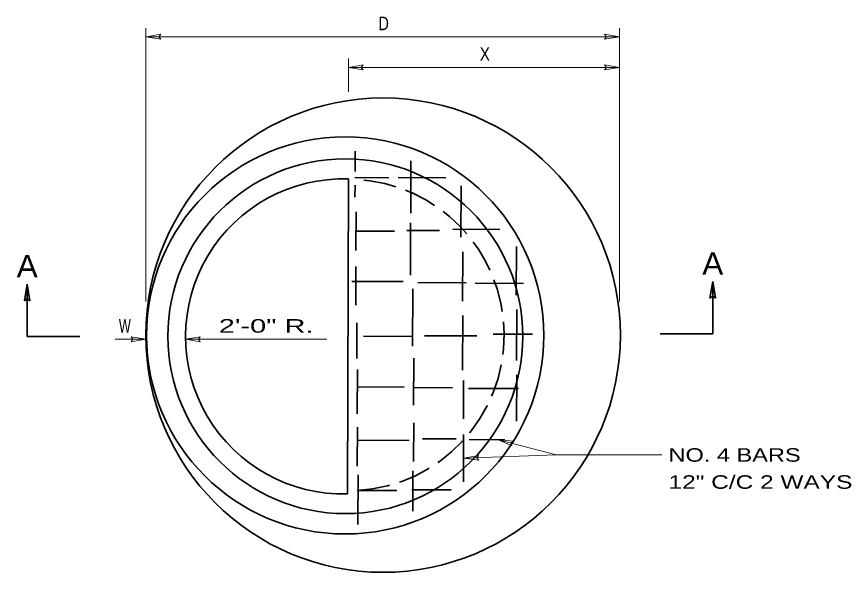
# Model space of a CAD drawing. Extents: x 5.1 to 20.2, y -16.7 to 4.3.
# Drawn here: x 8.84 to 16.79, y -1.01 to 4.29 of the extents above; entities that cross this region are included whole.
import ezdxf
from ezdxf.enums import TextEntityAlignment as Align

# ---------------------------------------------------------------- set-up
doc = ezdxf.new("R2010")
doc.units = 0
doc.header["$LTSCALE"] = 0.052
doc.linetypes.add('LONG_DASHED', pattern=[7.5, 6, -1.5])
for name, color, linetype, lineweight in [('1', 7, 'Continuous', 35), ('10', 7, 'Continuous', 13), ('12', 7, 'Continuous', 53), ('13', 7, 'Continuous', 25)]:
    doc.layers.add(name, color=color, linetype=linetype, lineweight=lineweight)

msp = doc.modelspace()

# ---------------------------------------------------------------- linework, layer by layer
at = {"layer": '1'}
for p, q in [((12.06667, 2.81283), (12.06725, 3.00625)), ((12.59708, 2.41433), (12.59867, 2.91242)), ((11.99417, -0.26183), (12.0035, 2.74092)), ((12.06542, 2.75375), (12.38817, 2.75275)), ((12.47617, 2.75342), (12.93158, 2.752)), ((12.06558, 2.56833), (12.06592, 2.68067)), ((13.07558, 2.18625), (13.07708, 2.67575)), ((12.07442, 2.05808), (12.07558, 2.428)), ((12.59442, 1.824), (12.596, 2.32117)), ((12.06617, 2.24458), (12.4425, 2.24342)), ((12.55992, 2.251), (12.8715, 2.25)), ((12.99908, 2.26067), (13.44625, 2.25925)), ((13.60225, 1.63342), (13.60367, 2.09742)), ((13.09108, 1.57483), (13.09258, 2.04492)), ((12.07308, 1.53792), (12.07425, 1.90483)), ((12.03467, 1.76458), (12.52433, 1.76308)), ((12.66592, 1.75358), (13.12342, 1.75217)), ((12.61358, 1.14642), (12.61533, 1.69367)), ((13.21225, 1.74683), (13.67117, 1.74542)), ((13.09017, 0.91742), (13.09183, 1.43958)), ((13.60558, 1.009), (13.60708, 1.49608)), ((12.08292, 1.02875), (12.084, 1.3685)), ((12.14658, 1.24108), (12.613, 1.23967)), ((12.72942, 1.24625), (13.22633, 1.24467)), ((13.38108, 1.26125), (13.75758, 1.26008)), ((12.62425, 0.58308), (12.62567, 1.03142)), ((12.08758, 0.50058), (12.08892, 0.9245)), ((13.09917, 0.45333), (13.10033, 0.81908)), ((13.605, 0.43167), (13.60642, 0.87375)), ((12.08267, 0.75817), (12.53492, 0.75675)), ((12.61592, 0.7515), (12.99333, 0.75033)), ((13.14808, 0.74483), (13.62367, 0.74333)), ((12.62383, 0.04783), (12.625, 0.41667)), ((12.08742, 0.00442), (12.08858, 0.37625)), ((12.0905, 0.25), (12.58133, 0.2485)), ((12.70883, 0.26408), (13.02858, 0.26308)), ((13.0985, -0.14508), (13.09992, 0.304)), ((13.15292, 0.25667), (13.492, 0.25558)), ((12.61567, -0.42717), (12.61683, -0.04025)), ((12.094, -0.55183), (12.0955, -0.08058)), ((12.08842, -0.22808), (12.46575, -0.22925)), ((12.6085, -0.22167), (12.98075, -0.22283))]:
    msp.add_line(p, q, dxfattribs=at)
for centre, radius in [((12.33329, 1.252), 2.26091), ((11.97213, 1.24913), 1.89255), ((11.97358, 1.24158), 1.69068)]:
    msp.add_circle(centre, radius, dxfattribs=at)
msp.add_arc((11.95382, 1.23968), 1.50206, 88.10465, 271.53917, dxfattribs=at)
at = {"layer": '1', "linetype": 'LONG_DASHED'}
msp.add_arc((12.00259, 1.25316), 1.48466, 273.27206, 87.73573, dxfattribs=at)
at = {"layer": '10'}
for p, q in [((10.07242, 1.57283), (10.07242, 4.17958)), ((14.58442, 1.57283), (14.58442, 4.17958)), ((10.21533, 4.11958), (10.07533, 4.09625)), ((10.07533, 4.09625), (14.58442, 4.09625)), ((10.21533, 4.07292), (10.07533, 4.09625)), ((10.21533, 4.11958), (10.19783, 4.09625)), ((10.21533, 4.07292), (10.19783, 4.09625)), ((14.44442, 4.11958), (14.58442, 4.09625)), ((14.44442, 4.11958), (14.46192, 4.09625)), ((14.44442, 4.07292), (14.58442, 4.09625)), ((14.44442, 4.07292), (14.46192, 4.09625)), ((12.0035, 3.57208), (12.0035, 3.88792)), ((12.1435, 3.82792), (12.0035, 3.80458)), ((12.1435, 3.82792), (12.126, 3.80458)), ((14.44442, 3.82792), (14.58442, 3.80458)), ((14.44442, 3.82792), (14.46192, 3.80458)), ((12.0035, 3.80458), (14.58442, 3.80458)), ((12.1435, 3.78125), (12.0035, 3.80458)), ((12.1435, 3.78125), (12.126, 3.80458)), ((14.44442, 3.78125), (14.58442, 3.80458)), ((14.44442, 3.78125), (14.46192, 3.80458)), ((9.78075, 1.21308), (10.07242, 1.21308)), ((9.93242, 1.23642), (10.07242, 1.21308)), ((9.93242, 1.23642), (9.94992, 1.21308)), ((9.93242, 1.18975), (10.07242, 1.21308)), ((9.93242, 1.18975), (9.94992, 1.21308)), ((10.59175, 1.23642), (10.45175, 1.21308)), ((10.45175, 1.21308), (11.7985, 1.21308)), ((10.59175, 1.18975), (10.45175, 1.21308)), ((10.59175, 1.23642), (10.57425, 1.21308)), ((10.59175, 1.18975), (10.57425, 1.21308)), ((13.98308, 0.10983), (13.4315, 0.25375)), ((13.56108, 0.19583), (13.4315, 0.25375)), ((13.57283, 0.241), (13.4315, 0.25375)), ((13.57283, 0.241), (13.55, 0.22283)), ((13.56108, 0.19583), (13.55, 0.22283)), ((13.98308, 0.10983), (13.10367, 0.07783)), ((13.24275, 0.10625), (13.10367, 0.07783)), ((13.24275, 0.10625), (13.22608, 0.08225)), ((13.24442, 0.05958), (13.22608, 0.08225)), ((13.98308, 0.10983), (14.99042, 0.10983)), ((13.24442, 0.05958), (13.10367, 0.07783))]:
    msp.add_line(p, q, dxfattribs=at)
at = {"layer": '10', "lineweight": 35}
for p, q in [((15.44742, 1.60458), (15.47458, 1.7645)), ((15.50075, 1.60442), (15.47458, 1.7645)), ((8.9155, 1.57958), (8.94267, 1.7395)), ((8.96883, 1.57942), (8.94267, 1.7395)), ((8.9155, 1.57958), (8.94225, 1.5995)), ((8.96883, 1.57942), (8.94225, 1.5995)), ((15.44742, 1.60458), (15.47417, 1.6245)), ((15.50075, 1.60442), (15.47417, 1.6245))]:
    msp.add_line(p, q, dxfattribs=at)
for points in [[(15.47458, 1.7645), (15.47458, 1.2645), (14.97458, 1.2645)], [(8.94267, 1.7395), (8.94267, 1.2395), (9.44267, 1.2395)]]:
    msp.add_lwpolyline(points, dxfattribs=at)

# ---------------------------------------------------------------- texts
at = {"layer": '12', "width": 1.05}
for p in [(8.94262, 1.802), (15.47454, 1.827)]:
    msp.add_text('A', height=0.215, dxfattribs=at).set_placement(p, align=Align.CENTER)
at = {"layer": '12'}
for s, width, p in [('NO. 4 BARS', 1.3, (15.05292, 0.04533)), ('12" C/C 2 WAYS', 1.35, (15.05292, -0.21267))]:
    msp.add_text(s, height=0.129, dxfattribs=dict(at, width=width)).set_placement(p)
at = {"layer": '13'}
for s, width, p in [('D', 0.8, (12.33883, 4.15875)), ('X', 0.85, (13.30292, 3.86708)), ('W', 0.7, (9.87317, 1.27558)), ('2\'-0" R.', 1.6, (11.21933, 1.27558))]:
    msp.add_text(s, height=0.129, dxfattribs=dict(at, width=width)).set_placement(p, align=Align.CENTER)

doc.saveas('drawing.dxf')
